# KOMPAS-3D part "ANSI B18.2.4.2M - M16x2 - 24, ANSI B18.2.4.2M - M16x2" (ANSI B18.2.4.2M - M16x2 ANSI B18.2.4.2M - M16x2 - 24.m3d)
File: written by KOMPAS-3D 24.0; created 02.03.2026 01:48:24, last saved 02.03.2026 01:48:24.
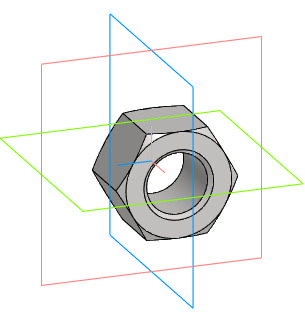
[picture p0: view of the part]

Document properties: Автор: R2D2; Полное имя файла: E:\Работа\Зайцев\GVWR3131M-2W-F-S Задвижка клиновая с выдвижным штоком DN.ru Ду50-200 Ру63\DN150\исходные материалы\ANSI B18.2.4.2M - M16x2 ANSI B18.2.4.2M - M16x2 - 24.m3d

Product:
- Body: Solid1  | qty 1
- Part/product: ANSI B18.2.4.2M - M16x2 - 24  | designation ANSI B18.2.4.2M - M16x2
    Комментарий: Типы метрических   шестигранных гаек   2
    additional columns: Сталь, мягкая

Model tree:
1. Solid1  (labels: Solid1)

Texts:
  ANSI B18.2.4.2M - M16x2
